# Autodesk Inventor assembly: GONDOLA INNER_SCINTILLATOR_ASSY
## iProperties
Shininess: 64.0
Length Units: 11272
Angle Units: 11279
Time Units: 11290
Mass Units: 11286
Length Display Precision: 3
Angle Display Precision: 2
Compacted: True
Part Number: GONDOLA INNER_SCINTILLATOR_ASSY
Document SubType Name: Assembly
Created: 2004-08
Designer: John Blackburn
Manufacturer: Standard
Standards Organization: Custom
Density: 0.0
Volumn: 0.0
Area: 0.0
PropertySet Name: Model Information
Control State: 0
Master: False
Checked Out: False
Author: John Blackburn
